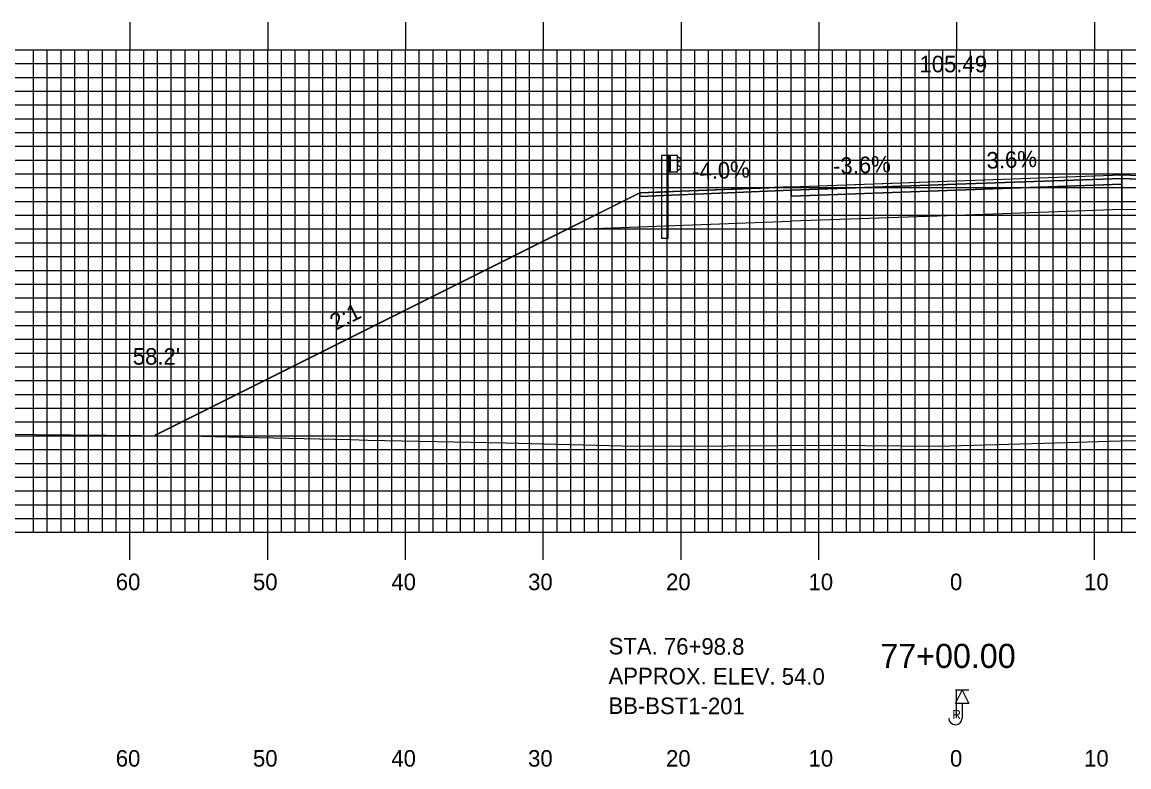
# Model space of a CAD drawing. Extents: x 1761791 to 1762134, y 442591 to 442811.
# Drawn here: x 1761888.9 to 1761969.3, y 442646.6 to 442700.7 of the extents above; entities that cross this region are included whole.
import ezdxf

# ---------------------------------------------------------------- set-up
doc = ezdxf.new("R2010")
doc.units = 0
for name, color, linetype in [('ANNOTATION', 7, 'Continuous'), ('BORING - REFUSAL', 7, 'Continuous'), ('D_Guardrail_Beam_Lt', 7, 'Continuous'), ('D_Roadway_Centerline', 7, 'Continuous'), ('D_Roadway_Centerline_Text', 7, 'Continuous'), ('D_Roadway_Edge_Shoulder', 7, 'Continuous'), ('D_Roadway_Edge_TW', 7, 'Continuous'), ('D_Roadway_Pavement', 7, 'Continuous'), ('D_Roadway_SlopeLines', 7, 'Continuous'), ('D_Roadway_SubGrade', 7, 'Continuous'), ('D_Text_Standard', 7, 'Continuous'), ('H_V ANNOTATION', 7, 'Continuous'), ('MAJOR', 7, 'Continuous'), ('MINOR', 7, 'Continuous'), ('S_Roadway_Centerline', 7, 'Continuous')]:
    doc.layers.add(name, color=color, linetype=linetype)

msp = doc.modelspace()

# ---------------------------------------------------------------- linework, layer by layer
at = {"layer": 'BORING - REFUSAL'}
for p, q in [((1761957.633, 442652.202), (1761956.673, 442652.202)), ((1761957.153, 442651.243), (1761957.153, 442650.184))]:
    msp.add_line(p, q, dxfattribs=at)
msp.add_lwpolyline([(1761957.153, 442652.202), (1761957.633, 442651.243), (1761956.673, 442651.243)], close=True, dxfattribs=at)
msp.add_arc((1761956.668, 442650.184), 0.485, 180, 0, dxfattribs=at)
at = {"layer": 'D_Guardrail_Beam_Lt'}
for p, q in [((1761935.324, 442690.987), (1761935.324, 442684.987)), ((1761935.795, 442690.987), (1761935.324, 442690.987)), ((1761936.482, 442690.987), (1761935.795, 442690.987)), ((1761935.795, 442690.987), (1761935.795, 442689.82)), ((1761935.857, 442690.987), (1761935.857, 442689.82)), ((1761935.961, 442690.987), (1761935.961, 442689.82)), ((1761936.482, 442689.82), (1761936.482, 442690.987)), ((1761936.482, 442690.903), (1761936.556, 442690.889)), ((1761936.572, 442690.882), (1761936.715, 442690.782)), ((1761936.486, 442690.438), (1761936.486, 442690.368)), ((1761936.715, 442690.639), (1761936.52, 442690.503)), ((1761936.52, 442690.304), (1761936.715, 442690.168)), ((1761936.715, 442690.024), (1761936.572, 442689.924)), ((1761935.795, 442689.82), (1761936.482, 442689.82)), ((1761935.815, 442684.987), (1761935.815, 442689.82)), ((1761936.556, 442689.918), (1761936.482, 442689.903)), ((1761935.815, 442684.987), (1761935.324, 442684.987))]:
    msp.add_line(p, q, dxfattribs=at)
for centre, major_axis, start_param, end_param in [((1761936.548, 442690.848), (0.0417, 0), 0.959931, 1.376053), ((1761936.665, 442690.71), (0.0877, 0), 5.323254, 7.243116), ((1761936.565, 442690.438), (-0.0789, 0), 5.323254, 6.283185), ((1761936.565, 442690.368), (-0.0789, 0), 6.283185, 7.243116), ((1761936.665, 442690.096), (0.0877, 0), 5.323254, 7.243116), ((1761936.548, 442689.958), (0.0417, 0), 4.907132, 5.323254)]:
    msp.add_ellipse(centre, major_axis=major_axis, ratio=0.995501, start_param=start_param, end_param=end_param, dxfattribs=at)
at = {"layer": 'D_Roadway_Centerline'}
msp.add_lwpolyline([(1761898.546, 442670.679), (1761898.548, 442670.68), (1761928.46, 442685.636), (1761928.462, 442685.637), (1761930.72, 442686.766), (1761933.753, 442688.283), (1761935.186, 442688.341), (1761936.753, 442688.403), (1761936.756, 442688.403), (1761943.127, 442688.658), (1761944.753, 442688.723), (1761953.322, 442689.032), (1761956.753, 442689.155), (1761968.749, 442689.587), (1761968.753, 442689.587), (1761968.756, 442689.587), (1761974.503, 442689.357)], dxfattribs=at)
at = {"layer": 'D_Roadway_Edge_Shoulder'}
for points in [[(1761968.753, 442689.587), (1761976.754, 442689.267), (1761976.754, 442689.267), (1761979.753, 442689.147), (1761979.753, 442688.897), (1761968.753, 442689.337)], [(1761944.753, 442688.723), (1761936.753, 442688.403), (1761936.753, 442688.403), (1761933.753, 442688.283), (1761933.753, 442688.033), (1761944.753, 442688.473)]]:
    msp.add_lwpolyline(points, close=True, dxfattribs=at)
at = {"layer": 'D_Roadway_Edge_TW'}
msp.add_lwpolyline([(1761944.753, 442688.473), (1761944.753, 442688.723), (1761956.753, 442689.155), (1761968.753, 442689.587), (1761968.753, 442689.337), (1761956.753, 442688.905)], close=True, dxfattribs=at)
at = {"layer": 'D_Roadway_Pavement'}
msp.add_lwpolyline([(1761944.753, 442688.056), (1761944.753, 442688.473), (1761956.753, 442688.905), (1761968.753, 442689.337), (1761968.753, 442688.92), (1761956.753, 442688.488)], close=True, dxfattribs=at)
for points in [[(1761968.753, 442689.337), (1761968.753, 442688.92)], [(1761944.753, 442688.473), (1761944.753, 442688.056)]]:
    msp.add_lwpolyline(points, dxfattribs=at)
at = {"layer": 'D_Roadway_SlopeLines'}
msp.add_lwpolyline([(1761933.753, 442688.283), (1761898.546, 442670.679)], dxfattribs=at)
at = {"layer": 'D_Roadway_SubGrade'}
for points in [[(1761944.753, 442686.223), (1761944.753, 442688.473), (1761944.753, 442688.056), (1761956.753, 442688.488), (1761968.753, 442688.92), (1761968.753, 442689.337), (1761968.753, 442687.087), (1761956.753, 442686.655)], [(1761968.753, 442688.92), (1761968.753, 442689.337), (1761979.753, 442688.897), (1761979.753, 442689.147), (1761984.503, 442686.772), (1761968.753, 442687.087)], [(1761944.753, 442688.056), (1761944.753, 442688.473), (1761933.753, 442688.033), (1761933.753, 442688.283), (1761928.46, 442685.636), (1761944.753, 442686.223)]]:
    msp.add_lwpolyline(points, close=True, dxfattribs=at)
at = {"layer": 'MAJOR'}
for p, q in [((1761896.753, 442700.669), (1761896.753, 442698.665)), ((1761906.753, 442700.669), (1761906.753, 442698.665)), ((1761916.753, 442700.669), (1761916.753, 442698.665)), ((1761926.753, 442700.669), (1761926.753, 442698.665)), ((1761936.753, 442700.669), (1761936.753, 442698.665)), ((1761946.753, 442700.669), (1761946.753, 442698.665)), ((1761956.753, 442700.669), (1761956.753, 442698.665)), ((1761966.753, 442700.669), (1761966.753, 442698.665)), ((1761816.753, 442698.665), (1762096.753, 442698.665)), ((1761816.753, 442698.665), (1762096.753, 442698.665)), ((1761896.753, 442663.665), (1761896.753, 442698.665)), ((1761906.753, 442663.665), (1761906.753, 442698.665)), ((1761916.753, 442663.665), (1761916.753, 442698.665)), ((1761926.753, 442663.665), (1761926.753, 442698.665)), ((1761936.753, 442663.665), (1761936.753, 442698.665)), ((1761946.753, 442663.665), (1761946.753, 442698.665)), ((1761956.753, 442663.665), (1761956.753, 442698.665)), ((1761966.753, 442663.665), (1761966.753, 442698.665)), ((1761816.753, 442693.665), (1762096.753, 442693.665)), ((1761816.753, 442688.665), (1762096.753, 442688.665)), ((1761816.753, 442683.665), (1762096.753, 442683.665)), ((1761816.753, 442678.665), (1762096.753, 442678.665)), ((1761816.753, 442673.665), (1762096.753, 442673.665)), ((1761816.753, 442668.665), (1762096.753, 442668.665)), ((1761816.753, 442663.665), (1762096.753, 442663.665)), ((1761816.753, 442663.665), (1762096.753, 442663.665)), ((1761896.753, 442661.661), (1761896.753, 442663.665)), ((1761906.753, 442661.661), (1761906.753, 442663.665)), ((1761916.753, 442661.661), (1761916.753, 442663.665)), ((1761926.753, 442661.661), (1761926.753, 442663.665)), ((1761936.753, 442661.661), (1761936.753, 442663.665)), ((1761946.753, 442661.661), (1761946.753, 442663.665)), ((1761966.753, 442661.661), (1761966.753, 442663.665)), ((1761956.753, 442650.198), (1761956.753, 442652.202))]:
    msp.add_line(p, q, dxfattribs=at)
at = {"layer": 'MINOR'}
for p, q in [((1761889.753, 442663.665), (1761889.753, 442698.665)), ((1761890.753, 442663.665), (1761890.753, 442698.665)), ((1761891.753, 442663.665), (1761891.753, 442698.665)), ((1761892.753, 442663.665), (1761892.753, 442698.665)), ((1761893.753, 442663.665), (1761893.753, 442698.665)), ((1761894.753, 442663.665), (1761894.753, 442698.665)), ((1761895.753, 442663.665), (1761895.753, 442698.665)), ((1761897.753, 442663.665), (1761897.753, 442698.665)), ((1761898.753, 442663.665), (1761898.753, 442698.665)), ((1761899.753, 442663.665), (1761899.753, 442698.665)), ((1761900.753, 442663.665), (1761900.753, 442698.665)), ((1761901.753, 442663.665), (1761901.753, 442698.665)), ((1761902.753, 442663.665), (1761902.753, 442698.665)), ((1761903.753, 442663.665), (1761903.753, 442698.665)), ((1761904.753, 442663.665), (1761904.753, 442698.665)), ((1761905.753, 442663.665), (1761905.753, 442698.665)), ((1761907.753, 442663.665), (1761907.753, 442698.665)), ((1761908.753, 442663.665), (1761908.753, 442698.665)), ((1761909.753, 442663.665), (1761909.753, 442698.665)), ((1761910.753, 442663.665), (1761910.753, 442698.665)), ((1761911.753, 442663.665), (1761911.753, 442698.665)), ((1761912.753, 442663.665), (1761912.753, 442698.665)), ((1761913.753, 442663.665), (1761913.753, 442698.665)), ((1761914.753, 442663.665), (1761914.753, 442698.665)), ((1761915.753, 442663.665), (1761915.753, 442698.665)), ((1761917.753, 442663.665), (1761917.753, 442698.665)), ((1761918.753, 442663.665), (1761918.753, 442698.665)), ((1761919.753, 442663.665), (1761919.753, 442698.665)), ((1761920.753, 442663.665), (1761920.753, 442698.665)), ((1761921.753, 442663.665), (1761921.753, 442698.665)), ((1761922.753, 442663.665), (1761922.753, 442698.665)), ((1761923.753, 442663.665), (1761923.753, 442698.665)), ((1761924.753, 442663.665), (1761924.753, 442698.665)), ((1761925.753, 442663.665), (1761925.753, 442698.665)), ((1761927.753, 442663.665), (1761927.753, 442698.665)), ((1761928.753, 442663.665), (1761928.753, 442698.665)), ((1761929.753, 442663.665), (1761929.753, 442698.665)), ((1761930.753, 442663.665), (1761930.753, 442698.665)), ((1761931.753, 442663.665), (1761931.753, 442698.665)), ((1761932.753, 442663.665), (1761932.753, 442698.665)), ((1761933.753, 442663.665), (1761933.753, 442698.665)), ((1761934.753, 442663.665), (1761934.753, 442698.665)), ((1761935.753, 442663.665), (1761935.753, 442698.665)), ((1761937.753, 442663.665), (1761937.753, 442698.665)), ((1761938.753, 442663.665), (1761938.753, 442698.665)), ((1761939.753, 442663.665), (1761939.753, 442698.665)), ((1761940.753, 442663.665), (1761940.753, 442698.665)), ((1761941.753, 442663.665), (1761941.753, 442698.665)), ((1761942.753, 442663.665), (1761942.753, 442698.665)), ((1761943.753, 442663.665), (1761943.753, 442698.665)), ((1761944.753, 442663.665), (1761944.753, 442698.665)), ((1761945.753, 442663.665), (1761945.753, 442698.665)), ((1761947.753, 442663.665), (1761947.753, 442698.665)), ((1761948.753, 442663.665), (1761948.753, 442698.665)), ((1761949.753, 442663.665), (1761949.753, 442698.665)), ((1761950.753, 442663.665), (1761950.753, 442698.665)), ((1761951.753, 442663.665), (1761951.753, 442698.665)), ((1761952.753, 442663.665), (1761952.753, 442698.665)), ((1761953.753, 442663.665), (1761953.753, 442698.665)), ((1761954.753, 442663.665), (1761954.753, 442698.665)), ((1761955.753, 442663.665), (1761955.753, 442698.665)), ((1761957.753, 442663.665), (1761957.753, 442698.665)), ((1761958.753, 442663.665), (1761958.753, 442698.665)), ((1761959.753, 442663.665), (1761959.753, 442698.665)), ((1761960.753, 442663.665), (1761960.753, 442698.665)), ((1761961.753, 442663.665), (1761961.753, 442698.665)), ((1761962.753, 442663.665), (1761962.753, 442698.665)), ((1761963.753, 442663.665), (1761963.753, 442698.665)), ((1761964.753, 442663.665), (1761964.753, 442698.665)), ((1761965.753, 442663.665), (1761965.753, 442698.665)), ((1761967.753, 442663.665), (1761967.753, 442698.665)), ((1761968.753, 442663.665), (1761968.753, 442698.665)), ((1761816.753, 442697.665), (1762096.753, 442697.665)), ((1761816.753, 442696.665), (1762096.753, 442696.665)), ((1761816.753, 442695.665), (1762096.753, 442695.665)), ((1761816.753, 442694.665), (1762096.753, 442694.665)), ((1761816.753, 442692.665), (1762096.753, 442692.665)), ((1761816.753, 442691.665), (1762096.753, 442691.665)), ((1761816.753, 442690.665), (1762096.753, 442690.665)), ((1761816.753, 442689.665), (1762096.753, 442689.665)), ((1761816.753, 442687.665), (1762096.753, 442687.665)), ((1761816.753, 442686.665), (1762096.753, 442686.665)), ((1761816.753, 442685.665), (1762096.753, 442685.665)), ((1761816.753, 442684.665), (1762096.753, 442684.665)), ((1761816.753, 442682.665), (1762096.753, 442682.665)), ((1761816.753, 442681.665), (1762096.753, 442681.665)), ((1761816.753, 442680.665), (1762096.753, 442680.665)), ((1761816.753, 442679.665), (1762096.753, 442679.665)), ((1761816.753, 442677.665), (1762096.753, 442677.665)), ((1761816.753, 442676.665), (1762096.753, 442676.665)), ((1761816.753, 442675.665), (1762096.753, 442675.665)), ((1761816.753, 442674.665), (1762096.753, 442674.665)), ((1761816.753, 442672.665), (1762096.753, 442672.665)), ((1761816.753, 442671.665), (1762096.753, 442671.665)), ((1761816.753, 442670.665), (1762096.753, 442670.665)), ((1761816.753, 442669.665), (1762096.753, 442669.665)), ((1761816.753, 442667.665), (1762096.753, 442667.665)), ((1761816.753, 442666.665), (1762096.753, 442666.665)), ((1761816.753, 442665.665), (1762096.753, 442665.665)), ((1761816.753, 442664.665), (1762096.753, 442664.665))]:
    msp.add_line(p, q, dxfattribs=at)
at = {"layer": 'S_Roadway_Centerline'}
msp.add_lwpolyline([(1761884.216, 442670.826), (1761889.892, 442670.765), (1761897.564, 442670.695), (1761901.953, 442670.627), (1761904.944, 442670.557), (1761912.739, 442670.404), (1761914.026, 442670.349), (1761924.006, 442670.142), (1761933.395, 442669.909), (1761934.733, 442669.946), (1761936.466, 442669.909), (1761947.441, 442669.988), (1761955.403, 442669.903), (1761963.08, 442670.12), (1761969.435, 442670.325), (1761975.596, 442670.103), (1761982.064, 442669.844), (1761989.419, 442670.085), (1761992.963, 442670.185), (1761995.404, 442670.245), (1762004.772, 442670.229), (1762015.952, 442670.536), (1762027.865, 442670.75)], dxfattribs=at)

# ---------------------------------------------------------------- texts
at = {"layer": 'ANNOTATION'}
for s, rotation, p in [('-3.6%', 2.06168, (1761947.802, 442689.634)), ('3.6%', 2.06168, (1761958.942, 442690.035)), ('-4.0%', 2.29055, (1761937.573, 442689.238)), ('2:1', 26.56494, (1761911.65, 442678.267))]:
    msp.add_text(s, height=1.2, rotation=rotation, dxfattribs=at).set_placement(p)
at = {"layer": 'BORING - REFUSAL'}
for s, p in [('STA. 76+98.8', (1761931.492, 442654.809)), ('APPROX. ELEV. 54.0', (1761931.485, 442652.649)), ('BB-BST1-201', (1761931.478, 442650.489))]:
    msp.add_text(s, height=1.2, rotation=359.81416, dxfattribs=at).set_placement(p)
msp.add_text('R', height=0.64, dxfattribs=at).set_placement((1761956.444, 442650.128))
at = {"layer": 'D_Roadway_Centerline'}
for s, p in [('C', (1761956.747, 442689.155)), ('L', (1761956.753, 442689.148))]:
    msp.add_text(s, height=0.0146, dxfattribs=at).set_placement(p)
at = {"layer": 'D_Roadway_Centerline_Text'}
msp.add_text('105.49', height=1.2, dxfattribs=at).set_placement((1761954.056, 442697.031))
at = {"layer": 'D_Text_Standard'}
msp.add_text("58.2'", height=1.2, dxfattribs=at).set_placement((1761896.961, 442675.822))
at = {"layer": 'H_V ANNOTATION'}
for s, height, p in [('60', 1.2, (1761895.725, 442659.465)), ('50', 1.2, (1761905.682, 442659.465)), ('40', 1.2, (1761915.725, 442659.465)), ('30', 1.2, (1761925.65, 442659.465)), ('20', 1.2, (1761935.661, 442659.465)), ('10', 1.2, (1761946.004, 442659.465)), ('0', 1.2, (1761956.271, 442659.465)), ('10', 1.2, (1761966.004, 442659.465)), ('77+00.00', 1.75, (1761951.212, 442653.821)), ('60', 1.2, (1761895.725, 442646.665)), ('50', 1.2, (1761905.682, 442646.665)), ('40', 1.2, (1761915.725, 442646.665)), ('30', 1.2, (1761925.65, 442646.665)), ('20', 1.2, (1761935.661, 442646.665)), ('10', 1.2, (1761946.004, 442646.665)), ('0', 1.2, (1761956.271, 442646.665)), ('10', 1.2, (1761966.004, 442646.665))]:
    msp.add_text(s, height=height, dxfattribs=at).set_placement(p)

doc.saveas('drawing.dxf')
